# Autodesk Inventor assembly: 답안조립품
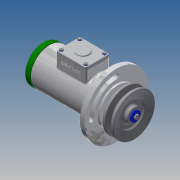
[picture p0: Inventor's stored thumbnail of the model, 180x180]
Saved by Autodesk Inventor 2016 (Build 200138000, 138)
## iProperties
Created: 2017-05
Part Number: 답안조립품
Document SubType Name: Assembly
Designer: Administrator
Author: Administrator
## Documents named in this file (20)
- D:\470507V1003\답안조립품.iam
- D:\470507V1003\본체.ipt
- D:\470507V1003\축.ipt
- D:\470507V1003\키 4 x 4 x 18.ipt
- D:\470507V1003\베어링 15 x 35 x 11.ipt
- D:\470507V1003\부시1.ipt
- D:\470507V1003\멈춤링 35x1.6.ipt
- D:\470507V1003\멈춤링 15 x 1.ipt
- D:\470507V1003\부시2.ipt
- D:\470507V1003\와셔 10x21.ipt
- D:\470507V1003\너트 M10.ipt
- D:\470507V1003\사이드 커버.ipt
- 사이드 커버.ipt
- D:\470507V1003\오일 실 15 25 7.ipt
- D:\470507V1003\V-벨트풀리.ipt
- D:\470507V1003\와셔 4x16.ipt
- D:\470507V1003\볼트 M4 x 10.ipt
- D:\470507V1003\탑 커버.ipt
- D:\470507V1003\와셔 3x6.ipt
- D:\470507V1003\십자볼트 M3 x 10.ipt
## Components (2 placed, 2 different names)
1. V-벨트풀리:1
2. ISO 4017 M4 x 10:1
